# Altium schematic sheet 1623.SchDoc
size A2
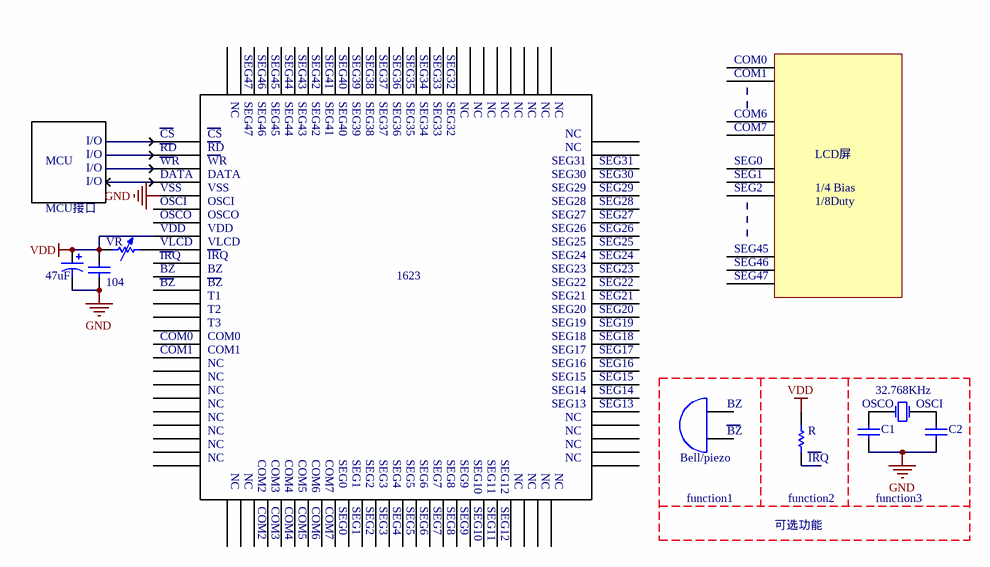
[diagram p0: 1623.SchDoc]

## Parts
(Parts that share a designator on the sheet are numbered #1, #2 ... from top to bottom, then left to right.)
C1  Cap  [RAD-0.3]  (value not drawn)
C2  Cap  [RAD-0.3]  (value not drawn)
C?#1  value 47uF  [RB7.6-15]  (hidden comment: Cap Pol1)
C?#2  value 104  [RAD-0.3]  (hidden comment: Cap)
LS?  Bell/piezo  [PIN2]
R  Res1  [AXIAL-0.3]  (value not drawn)
VR  Res Adj1  [AXIAL-0.7]  (value not drawn)
Y?  32.768KHz  [R38]

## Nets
GND: C1.1 C2.2 C?#1.2 C?#2.1
VDD: C?#1.1 C?#2.2 R.1 VR.1
NetC1_2: C1.2 Y?.1(OSC1)
NetC2_1: C2.1 Y?.2(OSC2)

Not connected (* = marked no-connect by the designer): LS? 1(A) 2(B); R 2; VR 2

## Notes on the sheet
- SEG47
- SEG46
- SEG45
- SEG44
- SEG43
- SEG42
- SEG41
- SEG40
- SEG39
- SEG38
- SEG37
- SEG36
- SEG35
- SEG34
- SEG33
- SEG32
- COM0
- COM1
- I/O
- RD
- CS
- NC
- COM6
- COM7
- MCU
- MCU接口
- WR
- DATA
- VSS
- (near VR) OSCI
- OSCI
- SEG30
- SEG28
- SEG31
- SEG29
- SEG2
- SEG1
- SEG0
- LCD屏
- 1/4 Bias
- 1/8Duty
- (near VR) VLCD
- (near VR) VDD
- (near VR) IRQ
- (near VR) BZ
- (near VR) OSCO
- VLCD
- VDD
- IRQ
- BZ
- OSCO
- 1623
- SEG26
- SEG27
- SEG25
- SEG23
- SEG24
- SEG22
- T1
- T2
- T3
- SEG19
- SEG18
- SEG21
- SEG20
- SEG14
- SEG13
- SEG15
- SEG16
- SEG17
- (near LS?) BZ
- COM2
- COM3
- COM4
- COM5
- SEG3
- SEG4
- SEG5
- SEG6
- SEG7
- SEG8
- SEG9
- SEG10
- SEG11
- SEG12
- (near R) IRQ
- function1
- 可选功能
- function2
- function3
- Labels drawn without touching a wire or pin: GND

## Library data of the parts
C1 C2 = Cap: Capacitor; Value: 104
C?#1 = Cap Pol1: Polarized Capacitor (Radial)
C?#2 = Cap: Capacitor
LS? = Bell: Electrical Bell
R = Res1: Resistor; Value: 1K
VR = Res Adj1: Variable Resistor; Value: 1K; Set Position: 0.5
Y? = XTAL: Crystal Oscillator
